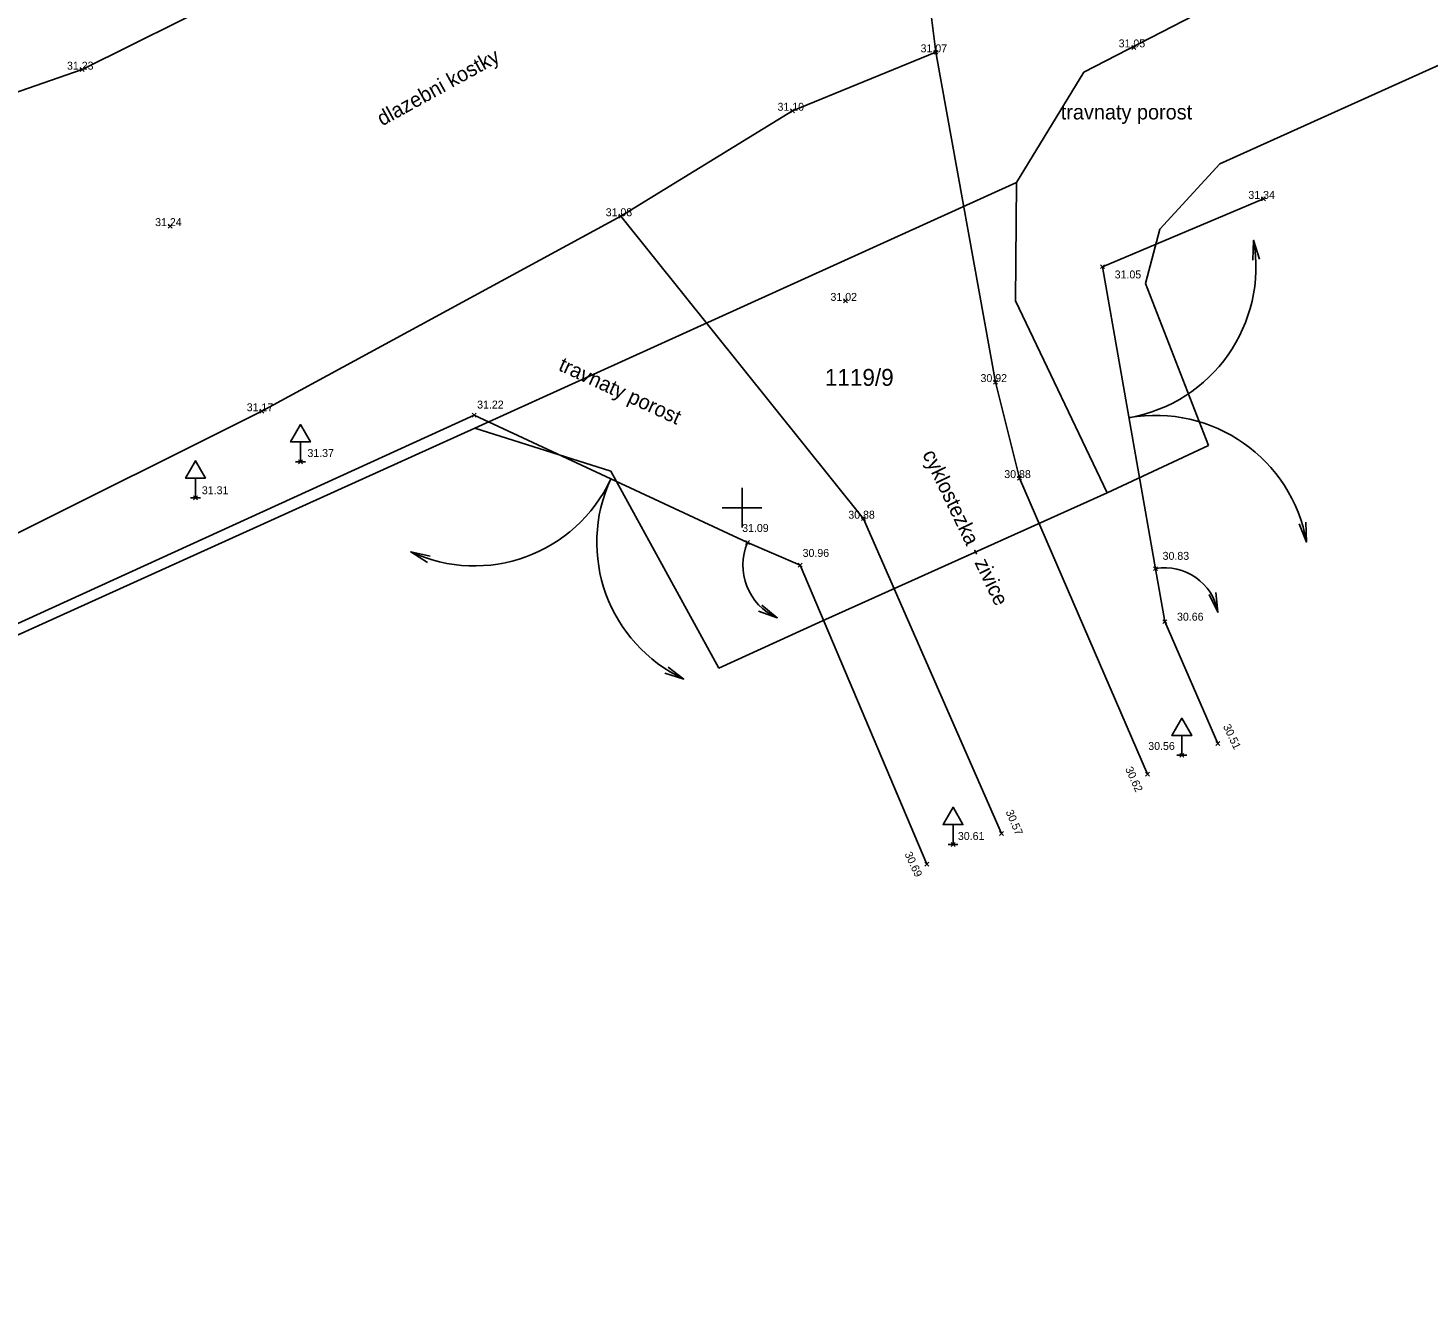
# Model space of a CAD drawing. Extents: x -772865 to -772533, y -1034366 to -1034132.
# Drawn here: x -772589.42 to -772561.15, y -1034240.84 to -1034215.31 of the extents above; entities that cross this region are included whole.
import ezdxf

# ---------------------------------------------------------------- set-up
doc = ezdxf.new("R2010")
doc.units = 0
for name, color, linetype in [('body', 7, 'Continuous'), ('dopravni_znacky', 7, 'Continuous'), ('KM_hranice', 7, 'Continuous'), ('KM_parcelni_cisla', 7, 'Continuous'), ('mistni_popis', 7, 'Continuous'), ('oddeleni_ploch', 7, 'Continuous'), ('oploceni', 7, 'Continuous'), ('souradnicova_sit', 7, 'Continuous'), ('vyskove_koty', 7, 'Continuous')]:
    doc.layers.add(name, color=color, linetype=linetype)

msp = doc.modelspace()

# ---------------------------------------------------------------- linework, layer by layer
at = {"layer": 'body'}
for p, q in [((-772571.05, -1034215.84), (-772571.13, -1034215.76)), ((-772571.13, -1034215.84), (-772571.05, -1034215.76)), ((-772567.05, -1034215.74), (-772567.13, -1034215.66)), ((-772567.13, -1034215.74), (-772567.05, -1034215.66)), ((-772588.29, -1034216.19), (-772588.37, -1034216.11)), ((-772588.37, -1034216.19), (-772588.29, -1034216.11)), ((-772573.94, -1034217.02), (-772574.02, -1034216.94)), ((-772574.02, -1034217.02), (-772573.94, -1034216.94)), ((-772564.43, -1034218.8), (-772564.51, -1034218.72)), ((-772564.51, -1034218.8), (-772564.43, -1034218.72)), ((-772586.51, -1034219.35), (-772586.59, -1034219.27)), ((-772586.59, -1034219.35), (-772586.51, -1034219.27)), ((-772577.41, -1034219.15), (-772577.49, -1034219.07)), ((-772577.49, -1034219.15), (-772577.41, -1034219.07)), ((-772567.68, -1034220.17), (-772567.76, -1034220.09)), ((-772567.76, -1034220.17), (-772567.68, -1034220.09)), ((-772572.87, -1034220.86), (-772572.95, -1034220.78)), ((-772572.95, -1034220.86), (-772572.87, -1034220.78)), ((-772569.84, -1034222.5), (-772569.92, -1034222.42)), ((-772569.92, -1034222.5), (-772569.84, -1034222.42)), ((-772584.66, -1034223.09), (-772584.74, -1034223.01)), ((-772584.74, -1034223.09), (-772584.66, -1034223.01)), ((-772580.37, -1034223.17), (-772580.45, -1034223.09)), ((-772580.45, -1034223.17), (-772580.37, -1034223.09)), ((-772583.88, -1034224.11), (-772583.96, -1034224.03)), ((-772583.96, -1034224.11), (-772583.88, -1034224.03)), ((-772569.36, -1034224.44), (-772569.44, -1034224.36)), ((-772569.44, -1034224.44), (-772569.36, -1034224.36)), ((-772586, -1034224.84), (-772586.08, -1034224.76)), ((-772586.08, -1034224.84), (-772586, -1034224.76)), ((-772572.51, -1034225.26), (-772572.59, -1034225.18)), ((-772572.59, -1034225.26), (-772572.51, -1034225.18)), ((-772574.85, -1034225.74), (-772574.93, -1034225.66)), ((-772574.93, -1034225.74), (-772574.85, -1034225.66)), ((-772573.79, -1034226.2), (-772573.87, -1034226.12)), ((-772573.87, -1034226.2), (-772573.79, -1034226.12)), ((-772566.61, -1034226.27), (-772566.69, -1034226.19)), ((-772566.69, -1034226.27), (-772566.61, -1034226.19)), ((-772566.42, -1034227.34), (-772566.5, -1034227.26)), ((-772566.5, -1034227.34), (-772566.42, -1034227.26)), ((-772565.35, -1034229.8), (-772565.43, -1034229.72)), ((-772565.43, -1034229.8), (-772565.35, -1034229.72)), ((-772566.08, -1034230.04), (-772566.16, -1034229.96)), ((-772566.16, -1034230.04), (-772566.08, -1034229.96)), ((-772566.77, -1034230.42), (-772566.85, -1034230.34)), ((-772566.85, -1034230.42), (-772566.77, -1034230.34)), ((-772569.72, -1034231.62), (-772569.8, -1034231.54)), ((-772569.8, -1034231.62), (-772569.72, -1034231.54)), ((-772570.7, -1034231.84), (-772570.78, -1034231.76)), ((-772570.78, -1034231.84), (-772570.7, -1034231.76)), ((-772571.23, -1034232.24), (-772571.31, -1034232.16)), ((-772571.31, -1034232.24), (-772571.23, -1034232.16))]:
    msp.add_line(p, q, dxfattribs=at)
at = {"layer": 'dopravni_znacky'}
for p, q in [((-772584.02, -1034224.07), (-772583.82, -1034224.07)), ((-772586.14, -1034224.8), (-772585.94, -1034224.8)), ((-772566.22, -1034230), (-772566.02, -1034230)), ((-772570.84, -1034231.8), (-772570.64, -1034231.8))]:
    msp.add_line(p, q, dxfattribs=at)
for points in [[(-772583.92, -1034224.07), (-772583.92, -1034223.67), (-772583.72, -1034223.67), (-772583.92, -1034223.32), (-772584.12, -1034223.67), (-772583.92, -1034223.67)], [(-772586.04, -1034224.8), (-772586.04, -1034224.4), (-772585.84, -1034224.4), (-772586.04, -1034224.05), (-772586.24, -1034224.4), (-772586.04, -1034224.4)], [(-772566.12, -1034230), (-772566.12, -1034229.6), (-772565.92, -1034229.6), (-772566.12, -1034229.25), (-772566.32, -1034229.6), (-772566.12, -1034229.6)], [(-772570.74, -1034231.8), (-772570.74, -1034231.4), (-772570.54, -1034231.4), (-772570.74, -1034231.05), (-772570.94, -1034231.4), (-772570.74, -1034231.4)]]:
    msp.add_lwpolyline(points, dxfattribs=at)
at = {"layer": 'KM_hranice'}
for p, q in [((-772565.35, -1034218.05), (-772532.872, -1034203.414)), ((-772565.86, -1034215.05), (-772568.1, -1034216.2)), ((-772568.1, -1034216.2), (-772569.46, -1034218.43)), ((-772566.56, -1034219.37), (-772565.35, -1034218.05)), ((-772569.46, -1034218.43), (-772580.4, -1034223.39)), ((-772569.48, -1034220.82), (-772569.46, -1034218.43)), ((-772566.85, -1034220.47), (-772566.56, -1034219.37)), ((-772565.58, -1034223.74), (-772566.85, -1034220.47)), ((-772567.63, -1034224.7), (-772569.48, -1034220.82)), ((-772597.14, -1034230.97), (-772580.4, -1034223.39)), ((-772580.4, -1034223.39), (-772577.65, -1034224.26)), ((-772567.63, -1034224.7), (-772565.58, -1034223.74)), ((-772577.65, -1034224.26), (-772575.47, -1034228.24)), ((-772573.45, -1034227.32), (-772567.63, -1034224.7)), ((-772575.47, -1034228.24), (-772573.45, -1034227.32))]:
    msp.add_line(p, q, dxfattribs=at)
at = {"layer": 'oddeleni_ploch'}
for points in [[(-772569.67, -1034207.72), (-772578.35, -1034211.18), (-772588.33, -1034216.15), (-772592.11, -1034217.46), (-772598.89, -1034219.1), (-772610.21, -1034219.57), (-772621.14, -1034219.48), (-772637.34, -1034221.06), (-772647.54, -1034222.08), (-772674.34, -1034233.24), (-772685.01, -1034239.21), (-772697.33, -1034242.95), (-772712.12, -1034249.56), (-772725.85, -1034254.8), (-772738.85, -1034261.98), (-772750.37, -1034267.76), (-772764, -1034272.65), (-772783.9, -1034280.59), (-772796.38, -1034286.28), (-772810.31, -1034291.67), (-772823.61, -1034294.35), (-772828.52, -1034296.12), (-772827.01, -1034302.81), (-772823.23, -1034300.75)], [(-772567.34, -1034212.16), (-772571.18, -1034215.04), (-772571.09, -1034215.8), (-772573.98, -1034216.98), (-772577.45, -1034219.11), (-772584.7, -1034223.05), (-772595.02, -1034228.2), (-772607.45, -1034233.93), (-772615.83, -1034237.74), (-772627.86, -1034242.86), (-772647.89, -1034252.03), (-772658, -1034256.56), (-772672.84, -1034263.1), (-772676.49, -1034257.87), (-772679.65, -1034256.43), (-772682.64, -1034256.79), (-772689.63, -1034259.88), (-772704.53, -1034266.45)], [(-772566.81, -1034230.38), (-772569.4, -1034224.4), (-772569.88, -1034222.46), (-772571.09, -1034215.8)], [(-772569.76, -1034231.58), (-772572.55, -1034225.22), (-772577.45, -1034219.11)]]:
    msp.add_lwpolyline(points, dxfattribs=at)
at = {"layer": 'oploceni'}
for p, q in [((-772567.72, -1034220.13), (-772564.47, -1034218.76)), ((-772567.72, -1034220.13), (-772566.65, -1034226.23)), ((-772574.89, -1034225.7), (-772580.41, -1034223.13)), ((-772573.83, -1034226.16), (-772574.89, -1034225.7)), ((-772571.27, -1034232.2), (-772573.83, -1034226.16)), ((-772566.65, -1034226.23), (-772566.46, -1034227.3)), ((-772565.39, -1034229.76), (-772566.46, -1034227.3))]:
    msp.add_line(p, q, dxfattribs=at)
for points in [[(-772564.548, -1034219.979), (-772564.67, -1034219.597), (-772564.686, -1034219.997)], [(-772580.41, -1034223.13), (-772594.37, -1034229.5), (-772606.44, -1034234.99), (-772615.35, -1034239.09), (-772626.89, -1034244.31), (-772647.29, -1034253.6), (-772657.19, -1034258.12), (-772675.87, -1034266.57), (-772700.9, -1034277.76), (-772711.36, -1034282.37), (-772727.94, -1034289.85)], [(-772563.752, -1034225.322), (-772563.6, -1034225.693), (-772563.616, -1034225.293)], [(-772581.303, -1034225.979), (-772581.693, -1034225.891), (-772581.356, -1034226.107)], [(-772565.567, -1034226.75), (-772565.39, -1034227.109), (-772565.433, -1034226.711)], [(-772574.669, -1034227.088), (-772574.291, -1034227.22), (-772574.601, -1034226.967)], [(-772576.559, -1034228.34), (-772576.177, -1034228.459), (-772576.496, -1034228.217)]]:
    msp.add_lwpolyline(points, dxfattribs=at)
for centre, radius, start, end in [((-772567.72, -1034220.13), 3.097, 279.949, 9.9034), ((-772566.65, -1034226.23), 3.097, 9.9947, 99.949), ((-772580.41, -1034223.13), 3.044, 245.0799, 335.0343), ((-772574.89, -1034225.7), 3.044, 155.0343, 244.9886), ((-772573.83, -1034226.16), 1.156, 156.541, 246.4954), ((-772566.46, -1034227.3), 1.087, 10.1147, 100.0691)]:
    msp.add_arc(centre, radius, start, end, dxfattribs=at)
at = {"layer": 'souradnicova_sit'}
for p, q in [((-772575, -1034224.6), (-772575, -1034225.4)), ((-772575.4, -1034225), (-772574.6, -1034225))]:
    msp.add_line(p, q, dxfattribs=at)

# ---------------------------------------------------------------- texts
at = {"layer": 'KM_parcelni_cisla'}
msp.add_text('1119/9', height=0.34, dxfattribs=at).set_placement((-772573.329, -1034222.536))
at = {"layer": 'mistni_popis'}
for s, rotation, p in [('dlazebni kostky', 28.8771, (-772582.269, -1034217.297)), ('travnaty porost', 335.2376, (-772578.729, -1034222.215)), ('cyklostezka - zivice', 295.7035, (-772571.365, -1034223.916))]:
    msp.add_text(s, height=0.3, rotation=rotation, dxfattribs=at).set_placement(p)
msp.add_text('travnaty porost', height=0.3, dxfattribs=at).set_placement((-772568.564, -1034217.156))
at = {"layer": 'vyskove_koty'}
for s, p in [('31.05', (-772567.395, -1034215.7)), ('31.07', (-772571.395, -1034215.8)), ('31.23', (-772588.635, -1034216.15)), ('31.10', (-772574.285, -1034216.98)), ('31.34', (-772564.775, -1034218.76)), ('31.08', (-772577.755, -1034219.11)), ('31.24', (-772586.855, -1034219.31)), ('31.05', (-772567.475, -1034220.367)), ('31.02', (-772573.215, -1034220.82)), ('30.92', (-772570.185, -1034222.46)), ('31.17', (-772585.005, -1034223.05)), ('31.22', (-772580.351, -1034222.995)), ('31.37', (-772583.779, -1034223.974)), ('30.88', (-772569.705, -1034224.4)), ('31.31', (-772585.911, -1034224.726)), ('30.88', (-772572.855, -1034225.22)), ('31.09', (-772574.999, -1034225.488)), ('30.96', (-772573.778, -1034225.992)), ('30.83', (-772566.507, -1034226.051)), ('30.66', (-772566.216, -1034227.28)), ('30.56', (-772566.797, -1034229.891)), ('30.61', (-772570.642, -1034231.71))]:
    msp.add_text(s, height=0.16, dxfattribs=at).set_placement(p)
for s, rotation, p in [('30.51', 295.4743, (-772565.291, -1034229.415)), ('30.62', 294.3857, (-772567.267, -1034230.273)), ('30.57', 293.3544, (-772569.681, -1034231.141)), ('30.69', 294.9014, (-772571.723, -1034231.991))]:
    msp.add_text(s, height=0.16, rotation=rotation, dxfattribs=at).set_placement(p)

doc.saveas('drawing.dxf')
